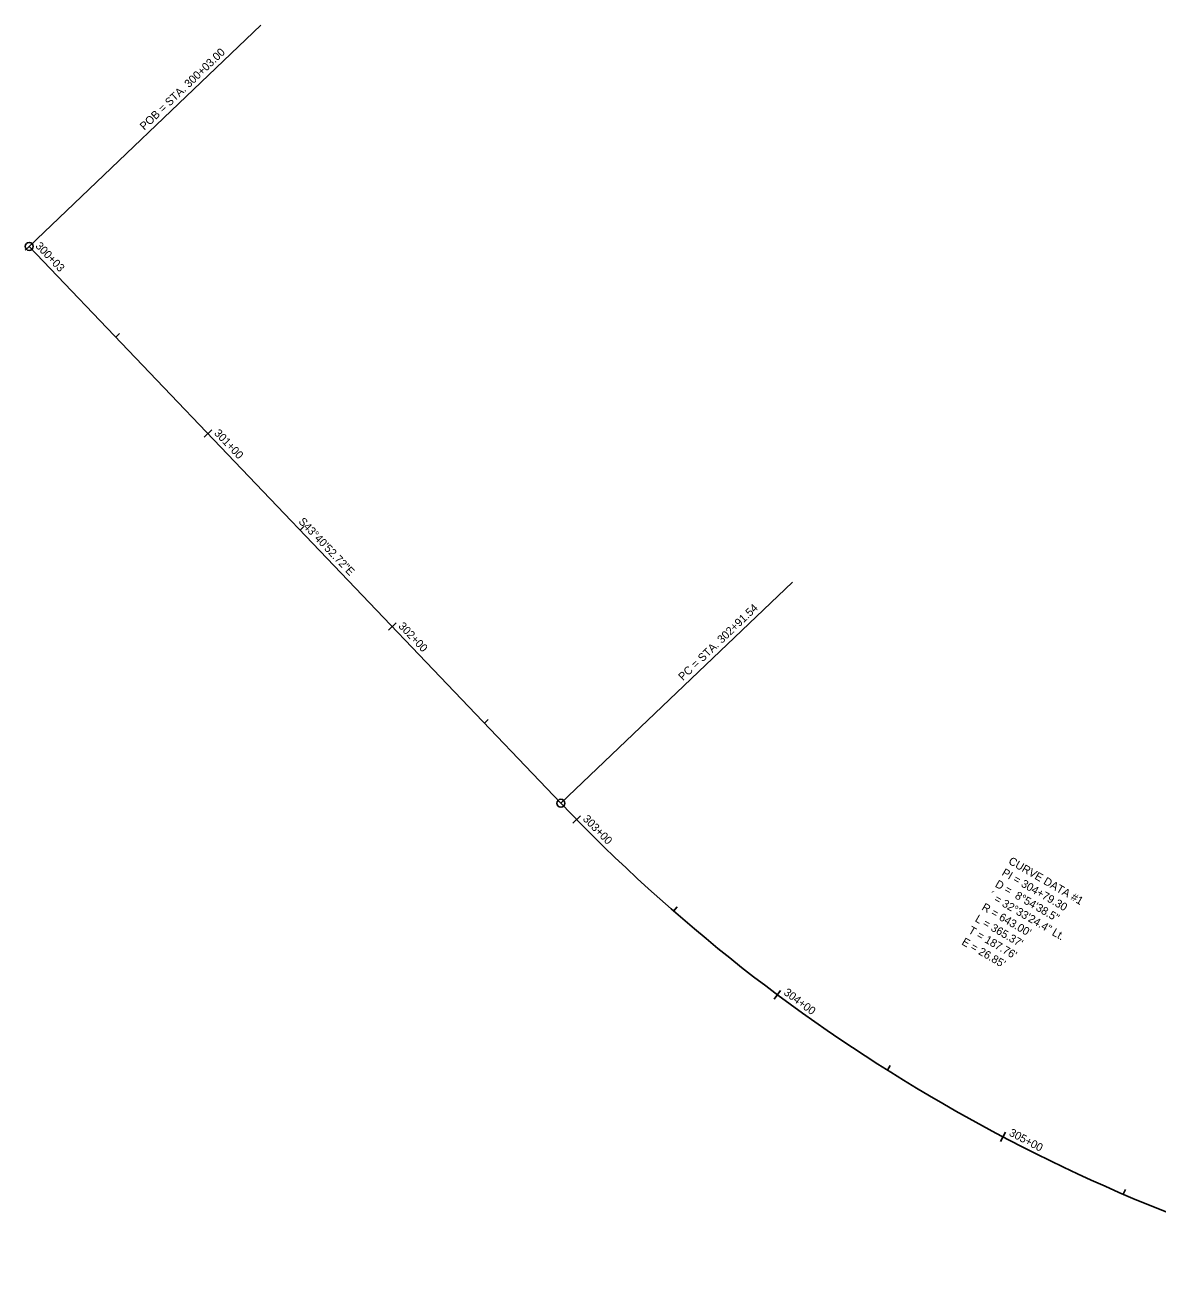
# Model space of a CAD drawing. Extents: x 1158481 to 1165348, y 610053 to 611824.
# Drawn here: x 1158481.5 to 1158906, y 611351.8 to 611823.8 of the extents above; entities that cross this region are included whole.
import ezdxf

# ---------------------------------------------------------------- set-up
doc = ezdxf.new("R2010")
doc.units = 0
for name, color, linetype in [('D_Roadway_Centerline', 7, 'Continuous'), ('D_Roadway_Centerline_Bearings', 7, 'Continuous'), ('D_Roadway_Centerline_CurveData', 7, 'Continuous'), ('D_Roadway_Centerline_Flags', 7, 'Continuous'), ('D_Roadway_Centerline_Text', 7, 'Continuous')]:
    doc.layers.add(name, color=color, linetype=linetype)

msp = doc.modelspace()

# ---------------------------------------------------------------- linework, layer by layer
at = {"layer": 'D_Roadway_Centerline'}
msp.add_line((1158482.99, 611740.88), (1158682.27, 611532.21), dxfattribs=at)
msp.add_arc((1159147.28, 611976.3), 643, 223.68131, 256.23809, dxfattribs=at)
at = {"layer": 'D_Roadway_Centerline_Flags'}
for points in [[(1158482.99, 611740.88), (1158569.77, 611823.76)], [(1158682.27, 611532.21), (1158769.05, 611615.09)]]:
    msp.add_lwpolyline(points, dxfattribs=at)
for centre in [(1158482.99, 611740.88), (1158682.27, 611532.21)]:
    msp.add_circle(centre, 1.5, dxfattribs=at)
at = {"layer": 'D_Roadway_Centerline_Text'}
for points in [[(1158484.44, 611742.26), (1158481.54, 611739.5)], [(1158484.44, 611742.26), (1158481.54, 611739.5)], [(1158516.9, 611708.27), (1158515.45, 611706.89)], [(1158551.43, 611672.11), (1158548.54, 611669.35)], [(1158585.96, 611635.95), (1158584.52, 611634.57)], [(1158620.49, 611599.79), (1158617.6, 611597.03)], [(1158655.03, 611563.63), (1158653.58, 611562.25)], [(1158689.58, 611527.53), (1158686.72, 611524.73)], [(1158725.83, 611493.33), (1158724.51, 611491.83)], [(1158764.62, 611462.05), (1158762.23, 611458.84)], [(1158805.72, 611433.88), (1158804.65, 611432.19)], [(1158848.89, 611408.99), (1158847.03, 611405.45)], [(1158893.86, 611387.52), (1158893.07, 611385.68)]]:
    msp.add_lwpolyline(points, dxfattribs=at)

# ---------------------------------------------------------------- texts
at = {"layer": 'D_Roadway_Centerline_Bearings'}
msp.add_text('S43%%d40\'52.72"E', height=3, rotation=313.6813, dxfattribs=at).set_placement((1158583.71, 611637.58))
at = {"layer": 'D_Roadway_Centerline_CurveData'}
for s, p in [('CURVE DATA #1', (1158849.74, 611509.72)), ('PI = 304+79.30', (1158847.24, 611505.39)), ('D =  8%%d54\'38.5"', (1158844.74, 611501.07)), ('´ = 32%%d33\'24.4" Lt.', (1158842.23, 611496.74)), ("R = 643.00'", (1158839.73, 611492.41)), ("L = 365.37'", (1158837.23, 611488.08)), ("T = 187.76'", (1158834.72, 611483.75)), ("E = 26.85'", (1158832.22, 611479.42))]:
    msp.add_text(s, height=3, rotation=329.9597, dxfattribs=at).set_placement(p)
at = {"layer": 'D_Roadway_Centerline_Flags'}
for s, p in [('POB = STA. 300+03.00', (1158526.18, 611784.2)), ('PC = STA. 302+91.54', (1158728, 611577.96))]:
    msp.add_text(s, height=3, rotation=43.6813, dxfattribs=at).set_placement(p)
at = {"layer": 'D_Roadway_Centerline_Text'}
for s, rotation, p in [('300+03', 313.6813, (1158485.11, 611740.83)), ('300+03', 313.6813, (1158485.11, 611740.83)), ('301+00', 313.6813, (1158552.1, 611670.68)), ('302+00', 313.6813, (1158621.17, 611598.36)), ('303+00', 314.4354, (1158690.27, 611526.11)), ('304+00', 323.346, (1158765.52, 611460.76)), ('305+00', 332.2567, (1158849.98, 611407.85))]:
    msp.add_text(s, height=3, rotation=rotation, dxfattribs=at).set_placement(p)

doc.saveas('drawing.dxf')
